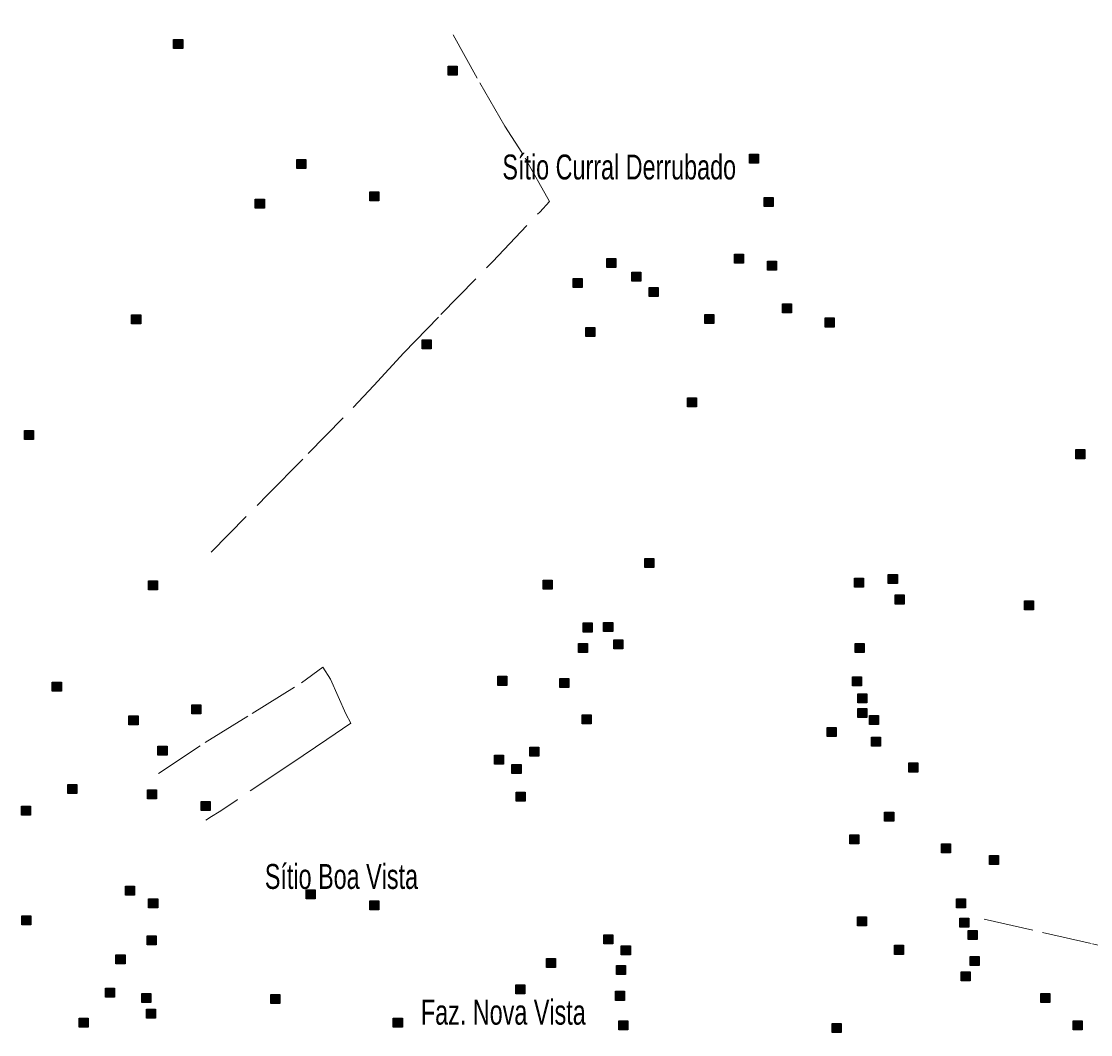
# Model space of a CAD drawing. Extents: x 445.6 to 500, y 8618.1 to 8673.4.
# Drawn here: x 453.66 to 460.52, y 8666.9 to 8673.4 of the extents above; entities that cross this region are included whole.
import ezdxf
from ezdxf.enums import TextEntityAlignment as Align

# ---------------------------------------------------------------- set-up
doc = ezdxf.new("R2010")
doc.units = 0
doc.header["$LTSCALE"] = 0.064
doc.linetypes.add('DOT_DASHED', pattern=[7.7, 5, -1.2, 0.3, -1.2])
doc.layers.add('2', color=7, linetype='Continuous', lineweight=25)
doc.layers.add('22', color=7, linetype='DOT_DASHED', lineweight=13)
doc.layers.add('61', color=7, linetype='Continuous')

msp = doc.modelspace()

# ---------------------------------------------------------------- hatches: boundary and pattern name
at = {"layer": '2'}
for points in [[(454.639, 8673.2829), (454.697, 8673.2829), (454.697, 8673.2249), (454.639, 8673.2249)], [(456.3999, 8673.113), (456.4579, 8673.113), (456.4579, 8673.055), (456.3999, 8673.055)], [(455.4294, 8672.5139), (455.4874, 8672.5139), (455.4874, 8672.4559), (455.4294, 8672.4559)], [(458.3303, 8672.5481), (458.3883, 8672.5481), (458.3883, 8672.4901), (458.3303, 8672.4901)], [(455.8966, 8672.3066), (455.9546, 8672.3066), (455.9546, 8672.2486), (455.8966, 8672.2486)], [(455.1625, 8672.2598), (455.2205, 8672.2598), (455.2205, 8672.2018), (455.1625, 8672.2018)], [(458.4248, 8672.2703), (458.4828, 8672.2703), (458.4828, 8672.2123), (458.4248, 8672.2123)], [(457.417, 8671.8794), (457.475, 8671.8794), (457.475, 8671.8214), (457.417, 8671.8214)], [(458.2345, 8671.9065), (458.2925, 8671.9065), (458.2925, 8671.8485), (458.2345, 8671.8485)], [(458.4473, 8671.8624), (458.5053, 8671.8624), (458.5053, 8671.8044), (458.4473, 8671.8044)], [(457.2009, 8671.7506), (457.2589, 8671.7506), (457.2589, 8671.6926), (457.2009, 8671.6926)], [(457.5758, 8671.7913), (457.6338, 8671.7913), (457.6338, 8671.7333), (457.5758, 8671.7333)], [(457.6872, 8671.6935), (457.7452, 8671.6935), (457.7452, 8671.6355), (457.6872, 8671.6355)], [(458.5419, 8671.588), (458.5999, 8671.588), (458.5999, 8671.53), (458.5419, 8671.53)], [(454.3697, 8671.517), (454.4277, 8671.517), (454.4277, 8671.459), (454.3697, 8671.459)], [(458.0453, 8671.5202), (458.1033, 8671.5202), (458.1033, 8671.4622), (458.0453, 8671.4622)], [(458.8167, 8671.4973), (458.8747, 8671.4973), (458.8747, 8671.4393), (458.8167, 8671.4393)], [(457.2819, 8671.4355), (457.3399, 8671.4355), (457.3399, 8671.3775), (457.2819, 8671.3775)], [(456.233, 8671.3579), (456.291, 8671.3579), (456.291, 8671.2999), (456.233, 8671.2999)], [(457.9339, 8670.9849), (457.9919, 8670.9849), (457.9919, 8670.9269), (457.9339, 8670.9269)], [(453.6823, 8670.7749), (453.7403, 8670.7749), (453.7403, 8670.7169), (453.6823, 8670.7169)], [(460.424, 8670.6529), (460.482, 8670.6529), (460.482, 8670.5949), (460.424, 8670.5949)], [(457.6596, 8669.9546), (457.7176, 8669.9546), (457.7176, 8669.8966), (457.6596, 8669.8966)], [(459.0051, 8669.8294), (459.0631, 8669.8294), (459.0631, 8669.7714), (459.0051, 8669.7714)], [(459.2213, 8669.8531), (459.2793, 8669.8531), (459.2793, 8669.7951), (459.2213, 8669.7951)], [(454.4777, 8669.8125), (454.5357, 8669.8125), (454.5357, 8669.7545), (454.4777, 8669.7545)], [(457.0077, 8669.8157), (457.0657, 8669.8157), (457.0657, 8669.7577), (457.0077, 8669.7577)], [(459.2652, 8669.7209), (459.3232, 8669.7209), (459.3232, 8669.6629), (459.2652, 8669.6629)], [(460.095, 8669.6837), (460.153, 8669.6837), (460.153, 8669.6257), (460.095, 8669.6257)], [(457.2644, 8669.5413), (457.3224, 8669.5413), (457.3224, 8669.4833), (457.2644, 8669.4833)], [(457.3961, 8669.5447), (457.4541, 8669.5447), (457.4541, 8669.4867), (457.3961, 8669.4867)], [(457.4603, 8669.4329), (457.5183, 8669.4329), (457.5183, 8669.3749), (457.4603, 8669.3749)], [(457.234, 8669.4091), (457.292, 8669.4091), (457.292, 8669.3511), (457.234, 8669.3511)], [(459.0085, 8669.4092), (459.0665, 8669.4092), (459.0665, 8669.3512), (459.0085, 8669.3512)], [(453.8609, 8669.1624), (453.9189, 8669.1624), (453.9189, 8669.1044), (453.8609, 8669.1044)], [(456.7172, 8669.1991), (456.7752, 8669.1991), (456.7752, 8669.1411), (456.7172, 8669.1411)], [(457.1158, 8669.1855), (457.1738, 8669.1855), (457.1738, 8669.1275), (457.1158, 8669.1275)], [(458.9916, 8669.1958), (459.0496, 8669.1958), (459.0496, 8669.1378), (458.9916, 8669.1378)], [(459.0254, 8669.0874), (459.0834, 8669.0874), (459.0834, 8669.0294), (459.0254, 8669.0294)], [(454.7547, 8669.0164), (454.8127, 8669.0164), (454.8127, 8668.9584), (454.7547, 8668.9584)], [(454.3527, 8668.9452), (454.4107, 8668.9452), (454.4107, 8668.8872), (454.3527, 8668.8872)], [(457.2576, 8668.9518), (457.3156, 8668.9518), (457.3156, 8668.8938), (457.2576, 8668.8938)], [(459.0254, 8668.9925), (459.0834, 8668.9925), (459.0834, 8668.9345), (459.0254, 8668.9345)], [(459.0997, 8668.9485), (459.1577, 8668.9485), (459.1577, 8668.8905), (459.0997, 8668.8905)], [(458.8295, 8668.8705), (458.8875, 8668.8705), (458.8875, 8668.8125), (458.8295, 8668.8125)], [(459.1132, 8668.8096), (459.1712, 8668.8096), (459.1712, 8668.7516), (459.1132, 8668.7516)], [(454.5385, 8668.7521), (454.5965, 8668.7521), (454.5965, 8668.6941), (454.5385, 8668.6941)], [(456.9232, 8668.7451), (456.9812, 8668.7451), (456.9812, 8668.6871), (456.9232, 8668.6871)], [(456.6969, 8668.6943), (456.7549, 8668.6943), (456.7549, 8668.6363), (456.6969, 8668.6363)], [(456.8084, 8668.6333), (456.8664, 8668.6333), (456.8664, 8668.5753), (456.8084, 8668.5753)], [(459.353, 8668.6435), (459.411, 8668.6435), (459.411, 8668.5855), (459.353, 8668.5855)], [(453.9609, 8668.5048), (454.0189, 8668.5048), (454.0189, 8668.4468), (453.9609, 8668.4468)], [(454.4709, 8668.4709), (454.5289, 8668.4709), (454.5289, 8668.4129), (454.4709, 8668.4129)], [(456.8354, 8668.4571), (456.8934, 8668.4571), (456.8934, 8668.3991), (456.8354, 8668.3991)], [(454.8155, 8668.3964), (454.8735, 8668.3964), (454.8735, 8668.3384), (454.8155, 8668.3384)], [(453.6627, 8668.3671), (453.7207, 8668.3671), (453.7207, 8668.3091), (453.6627, 8668.3091)], [(459.1977, 8668.3285), (459.2557, 8668.3285), (459.2557, 8668.2705), (459.1977, 8668.2705)], [(458.9747, 8668.1828), (459.0327, 8668.1828), (459.0327, 8668.1248), (458.9747, 8668.1248)], [(459.5625, 8668.1252), (459.6205, 8668.1252), (459.6205, 8668.0672), (459.5625, 8668.0672)], [(459.8706, 8668.05), (459.9286, 8668.05), (459.9286, 8667.992), (459.8706, 8667.992)], [(454.33, 8667.8536), (454.388, 8667.8536), (454.388, 8667.7956), (454.33, 8667.7956)], [(454.4786, 8667.7722), (454.5366, 8667.7722), (454.5366, 8667.7142), (454.4786, 8667.7142)], [(455.4876, 8667.8298), (455.5456, 8667.8298), (455.5456, 8667.7718), (455.4876, 8667.7718)], [(459.6581, 8667.7723), (459.7161, 8667.7723), (459.7161, 8667.7143), (459.6581, 8667.7143)], [(455.8963, 8667.7587), (455.9543, 8667.7587), (455.9543, 8667.7007), (455.8963, 8667.7007)], [(453.6657, 8667.6639), (453.7237, 8667.6639), (453.7237, 8667.6059), (453.6657, 8667.6059)], [(459.0237, 8667.6571), (459.0817, 8667.6571), (459.0817, 8667.5991), (459.0237, 8667.5991)], [(459.6803, 8667.6491), (459.7383, 8667.6491), (459.7383, 8667.5911), (459.6803, 8667.5911)], [(459.7324, 8667.569), (459.7904, 8667.569), (459.7904, 8667.511), (459.7324, 8667.511)], [(454.4685, 8667.5351), (454.5265, 8667.5351), (454.5265, 8667.4771), (454.4685, 8667.4771)], [(457.3967, 8667.5419), (457.4547, 8667.5419), (457.4547, 8667.4839), (457.3967, 8667.4839)], [(457.5093, 8667.4703), (457.5673, 8667.4703), (457.5673, 8667.4123), (457.5093, 8667.4123)], [(459.2601, 8667.4741), (459.3181, 8667.4741), (459.3181, 8667.4161), (459.2601, 8667.4161)], [(454.2692, 8667.4131), (454.3272, 8667.4131), (454.3272, 8667.3551), (454.2692, 8667.3551)], [(457.0297, 8667.389), (457.0877, 8667.389), (457.0877, 8667.331), (457.0297, 8667.331)], [(459.7459, 8667.403), (459.8039, 8667.403), (459.8039, 8667.345), (459.7459, 8667.345)], [(457.4789, 8667.345), (457.5369, 8667.345), (457.5369, 8667.287), (457.4789, 8667.287)], [(459.6885, 8667.3047), (459.7465, 8667.3047), (459.7465, 8667.2467), (459.6885, 8667.2467)], [(456.8326, 8667.22), (456.8906, 8667.22), (456.8906, 8667.162), (456.8326, 8667.162)], [(454.2016, 8667.1997), (454.2596, 8667.1997), (454.2596, 8667.1417), (454.2016, 8667.1417)], [(454.4347, 8667.1658), (454.4927, 8667.1658), (454.4927, 8667.1078), (454.4347, 8667.1078)], [(455.2613, 8667.159), (455.3193, 8667.159), (455.3193, 8667.101), (455.2613, 8667.101)], [(457.4722, 8667.179), (457.5302, 8667.179), (457.5302, 8667.121), (457.4722, 8667.121)], [(460.1986, 8667.1658), (460.2566, 8667.1658), (460.2566, 8667.1078), (460.1986, 8667.1078)], [(454.4651, 8667.0641), (454.5231, 8667.0641), (454.5231, 8667.0061), (454.4651, 8667.0061)], [(454.0338, 8667.0066), (454.0918, 8667.0066), (454.0918, 8666.9486), (454.0338, 8666.9486)], [(456.0474, 8667.0065), (456.1054, 8667.0065), (456.1054, 8666.9485), (456.0474, 8666.9485)], [(457.4924, 8666.9892), (457.5504, 8666.9892), (457.5504, 8666.9312), (457.4924, 8666.9312)], [(458.8615, 8666.9727), (458.9195, 8666.9727), (458.9195, 8666.9147), (458.8615, 8666.9147)], [(460.4058, 8666.9896), (460.4638, 8666.9896), (460.4638, 8666.9316), (460.4058, 8666.9316)]]:
    msp.add_hatch(color=256, dxfattribs=at).paths.add_polyline_path(points)

# ---------------------------------------------------------------- linework, layer by layer
for points in [[(454.639, 8673.2829), (454.697, 8673.2829), (454.697, 8673.2249), (454.639, 8673.2249)], [(456.3999, 8673.113), (456.4579, 8673.113), (456.4579, 8673.055), (456.3999, 8673.055)], [(455.4294, 8672.5139), (455.4874, 8672.5139), (455.4874, 8672.4559), (455.4294, 8672.4559)], [(458.3303, 8672.5481), (458.3883, 8672.5481), (458.3883, 8672.4901), (458.3303, 8672.4901)], [(455.8966, 8672.3066), (455.9546, 8672.3066), (455.9546, 8672.2486), (455.8966, 8672.2486)], [(455.1625, 8672.2598), (455.2205, 8672.2598), (455.2205, 8672.2018), (455.1625, 8672.2018)], [(458.4248, 8672.2703), (458.4828, 8672.2703), (458.4828, 8672.2123), (458.4248, 8672.2123)], [(457.417, 8671.8794), (457.475, 8671.8794), (457.475, 8671.8214), (457.417, 8671.8214)], [(458.2345, 8671.9065), (458.2925, 8671.9065), (458.2925, 8671.8485), (458.2345, 8671.8485)], [(458.4473, 8671.8624), (458.5053, 8671.8624), (458.5053, 8671.8044), (458.4473, 8671.8044)], [(457.2009, 8671.7506), (457.2589, 8671.7506), (457.2589, 8671.6926), (457.2009, 8671.6926)], [(457.5758, 8671.7913), (457.6338, 8671.7913), (457.6338, 8671.7333), (457.5758, 8671.7333)], [(457.6872, 8671.6935), (457.7452, 8671.6935), (457.7452, 8671.6355), (457.6872, 8671.6355)], [(458.5419, 8671.588), (458.5999, 8671.588), (458.5999, 8671.53), (458.5419, 8671.53)], [(454.3697, 8671.517), (454.4277, 8671.517), (454.4277, 8671.459), (454.3697, 8671.459)], [(458.0453, 8671.5202), (458.1033, 8671.5202), (458.1033, 8671.4622), (458.0453, 8671.4622)], [(458.8167, 8671.4973), (458.8747, 8671.4973), (458.8747, 8671.4393), (458.8167, 8671.4393)], [(457.2819, 8671.4355), (457.3399, 8671.4355), (457.3399, 8671.3775), (457.2819, 8671.3775)], [(456.233, 8671.3579), (456.291, 8671.3579), (456.291, 8671.2999), (456.233, 8671.2999)], [(457.9339, 8670.9849), (457.9919, 8670.9849), (457.9919, 8670.9269), (457.9339, 8670.9269)], [(453.6823, 8670.7749), (453.7403, 8670.7749), (453.7403, 8670.7169), (453.6823, 8670.7169)], [(460.424, 8670.6529), (460.482, 8670.6529), (460.482, 8670.5949), (460.424, 8670.5949)], [(457.6596, 8669.9546), (457.7176, 8669.9546), (457.7176, 8669.8966), (457.6596, 8669.8966)], [(459.0051, 8669.8294), (459.0631, 8669.8294), (459.0631, 8669.7714), (459.0051, 8669.7714)], [(459.2213, 8669.8531), (459.2793, 8669.8531), (459.2793, 8669.7951), (459.2213, 8669.7951)], [(454.4777, 8669.8125), (454.5357, 8669.8125), (454.5357, 8669.7545), (454.4777, 8669.7545)], [(457.0077, 8669.8157), (457.0657, 8669.8157), (457.0657, 8669.7577), (457.0077, 8669.7577)], [(459.2652, 8669.7209), (459.3232, 8669.7209), (459.3232, 8669.6629), (459.2652, 8669.6629)], [(460.095, 8669.6837), (460.153, 8669.6837), (460.153, 8669.6257), (460.095, 8669.6257)], [(457.2644, 8669.5413), (457.3224, 8669.5413), (457.3224, 8669.4833), (457.2644, 8669.4833)], [(457.3961, 8669.5447), (457.4541, 8669.5447), (457.4541, 8669.4867), (457.3961, 8669.4867)], [(457.4603, 8669.4329), (457.5183, 8669.4329), (457.5183, 8669.3749), (457.4603, 8669.3749)], [(457.234, 8669.4091), (457.292, 8669.4091), (457.292, 8669.3511), (457.234, 8669.3511)], [(459.0085, 8669.4092), (459.0665, 8669.4092), (459.0665, 8669.3512), (459.0085, 8669.3512)], [(453.8609, 8669.1624), (453.9189, 8669.1624), (453.9189, 8669.1044), (453.8609, 8669.1044)], [(456.7172, 8669.1991), (456.7752, 8669.1991), (456.7752, 8669.1411), (456.7172, 8669.1411)], [(457.1158, 8669.1855), (457.1738, 8669.1855), (457.1738, 8669.1275), (457.1158, 8669.1275)], [(458.9916, 8669.1958), (459.0496, 8669.1958), (459.0496, 8669.1378), (458.9916, 8669.1378)], [(459.0254, 8669.0874), (459.0834, 8669.0874), (459.0834, 8669.0294), (459.0254, 8669.0294)], [(454.7547, 8669.0164), (454.8127, 8669.0164), (454.8127, 8668.9584), (454.7547, 8668.9584)], [(454.3527, 8668.9452), (454.4107, 8668.9452), (454.4107, 8668.8872), (454.3527, 8668.8872)], [(457.2576, 8668.9518), (457.3156, 8668.9518), (457.3156, 8668.8938), (457.2576, 8668.8938)], [(459.0254, 8668.9925), (459.0834, 8668.9925), (459.0834, 8668.9345), (459.0254, 8668.9345)], [(459.0997, 8668.9485), (459.1577, 8668.9485), (459.1577, 8668.8905), (459.0997, 8668.8905)], [(458.8295, 8668.8705), (458.8875, 8668.8705), (458.8875, 8668.8125), (458.8295, 8668.8125)], [(459.1132, 8668.8096), (459.1712, 8668.8096), (459.1712, 8668.7516), (459.1132, 8668.7516)], [(454.5385, 8668.7521), (454.5965, 8668.7521), (454.5965, 8668.6941), (454.5385, 8668.6941)], [(456.9232, 8668.7451), (456.9812, 8668.7451), (456.9812, 8668.6871), (456.9232, 8668.6871)], [(456.6969, 8668.6943), (456.7549, 8668.6943), (456.7549, 8668.6363), (456.6969, 8668.6363)], [(456.8084, 8668.6333), (456.8664, 8668.6333), (456.8664, 8668.5753), (456.8084, 8668.5753)], [(459.353, 8668.6435), (459.411, 8668.6435), (459.411, 8668.5855), (459.353, 8668.5855)], [(453.9609, 8668.5048), (454.0189, 8668.5048), (454.0189, 8668.4468), (453.9609, 8668.4468)], [(454.4709, 8668.4709), (454.5289, 8668.4709), (454.5289, 8668.4129), (454.4709, 8668.4129)], [(456.8354, 8668.4571), (456.8934, 8668.4571), (456.8934, 8668.3991), (456.8354, 8668.3991)], [(454.8155, 8668.3964), (454.8735, 8668.3964), (454.8735, 8668.3384), (454.8155, 8668.3384)], [(453.6627, 8668.3671), (453.7207, 8668.3671), (453.7207, 8668.3091), (453.6627, 8668.3091)], [(459.1977, 8668.3285), (459.2557, 8668.3285), (459.2557, 8668.2705), (459.1977, 8668.2705)], [(458.9747, 8668.1828), (459.0327, 8668.1828), (459.0327, 8668.1248), (458.9747, 8668.1248)], [(459.5625, 8668.1252), (459.6205, 8668.1252), (459.6205, 8668.0672), (459.5625, 8668.0672)], [(459.8706, 8668.05), (459.9286, 8668.05), (459.9286, 8667.992), (459.8706, 8667.992)], [(454.33, 8667.8536), (454.388, 8667.8536), (454.388, 8667.7956), (454.33, 8667.7956)], [(454.4786, 8667.7722), (454.5366, 8667.7722), (454.5366, 8667.7142), (454.4786, 8667.7142)], [(455.4876, 8667.8298), (455.5456, 8667.8298), (455.5456, 8667.7718), (455.4876, 8667.7718)], [(459.6581, 8667.7723), (459.7161, 8667.7723), (459.7161, 8667.7143), (459.6581, 8667.7143)], [(455.8963, 8667.7587), (455.9543, 8667.7587), (455.9543, 8667.7007), (455.8963, 8667.7007)], [(453.6657, 8667.6639), (453.7237, 8667.6639), (453.7237, 8667.6059), (453.6657, 8667.6059)], [(459.0237, 8667.6571), (459.0817, 8667.6571), (459.0817, 8667.5991), (459.0237, 8667.5991)], [(459.6803, 8667.6491), (459.7383, 8667.6491), (459.7383, 8667.5911), (459.6803, 8667.5911)], [(459.7324, 8667.569), (459.7904, 8667.569), (459.7904, 8667.511), (459.7324, 8667.511)], [(454.4685, 8667.5351), (454.5265, 8667.5351), (454.5265, 8667.4771), (454.4685, 8667.4771)], [(457.3967, 8667.5419), (457.4547, 8667.5419), (457.4547, 8667.4839), (457.3967, 8667.4839)], [(457.5093, 8667.4703), (457.5673, 8667.4703), (457.5673, 8667.4123), (457.5093, 8667.4123)], [(459.2601, 8667.4741), (459.3181, 8667.4741), (459.3181, 8667.4161), (459.2601, 8667.4161)], [(454.2692, 8667.4131), (454.3272, 8667.4131), (454.3272, 8667.3551), (454.2692, 8667.3551)], [(457.0297, 8667.389), (457.0877, 8667.389), (457.0877, 8667.331), (457.0297, 8667.331)], [(459.7459, 8667.403), (459.8039, 8667.403), (459.8039, 8667.345), (459.7459, 8667.345)], [(457.4789, 8667.345), (457.5369, 8667.345), (457.5369, 8667.287), (457.4789, 8667.287)], [(459.6885, 8667.3047), (459.7465, 8667.3047), (459.7465, 8667.2467), (459.6885, 8667.2467)], [(456.8326, 8667.22), (456.8906, 8667.22), (456.8906, 8667.162), (456.8326, 8667.162)], [(454.2016, 8667.1997), (454.2596, 8667.1997), (454.2596, 8667.1417), (454.2016, 8667.1417)], [(454.4347, 8667.1658), (454.4927, 8667.1658), (454.4927, 8667.1078), (454.4347, 8667.1078)], [(455.2613, 8667.159), (455.3193, 8667.159), (455.3193, 8667.101), (455.2613, 8667.101)], [(457.4722, 8667.179), (457.5302, 8667.179), (457.5302, 8667.121), (457.4722, 8667.121)], [(460.1986, 8667.1658), (460.2566, 8667.1658), (460.2566, 8667.1078), (460.1986, 8667.1078)], [(454.4651, 8667.0641), (454.5231, 8667.0641), (454.5231, 8667.0061), (454.4651, 8667.0061)], [(454.0338, 8667.0066), (454.0918, 8667.0066), (454.0918, 8666.9486), (454.0338, 8666.9486)], [(456.0474, 8667.0065), (456.1054, 8667.0065), (456.1054, 8666.9485), (456.0474, 8666.9485)], [(457.4924, 8666.9892), (457.5504, 8666.9892), (457.5504, 8666.9312), (457.4924, 8666.9312)], [(458.8615, 8666.9727), (458.9195, 8666.9727), (458.9195, 8666.9147), (458.8615, 8666.9147)], [(460.4058, 8666.9896), (460.4638, 8666.9896), (460.4638, 8666.9316), (460.4058, 8666.9316)]]:
    msp.add_lwpolyline(points, close=True, dxfattribs=at)
at = {"layer": '22'}
for points in [[(454.8787, 8669.996), (455.2436, 8670.3646), (455.5025, 8670.6273), (455.791, 8670.9239), (455.9226, 8671.0637), (456.1144, 8671.2733), (456.352, 8671.5191), (456.683, 8671.858), (456.9863, 8672.1769), (457.0498, 8672.244), (456.871, 8672.5593), (456.7627, 8672.7271), (456.586, 8673.0343), (456.3834, 8673.3994)], [(454.5421, 8668.575), (454.8418, 8668.7756), (455.1418, 8668.96), (455.4584, 8669.1576), (455.5947, 8669.2575), (455.6442, 8669.1817), (455.7431, 8668.9578), (455.7761, 8668.8986), (455.6211, 8668.7932), (455.3969, 8668.6417), (455.0432, 8668.406), (454.9311, 8668.3303), (454.8816, 8668.3007), (454.8443, 8668.2757)], [(459.8363, 8667.6409), (460.2101, 8667.5563), (460.5302, 8667.4836), (460.809, 8667.4207), (460.8372, 8667.4129), (460.8493, 8667.1078), (460.8469, 8666.8609), (460.8609, 8666.5929), (460.8658, 8666.3217), (460.8732, 8666.1144), (460.8877, 8665.7585), (460.8831, 8665.5131)]]:
    msp.add_lwpolyline(points, dxfattribs=at)

# ---------------------------------------------------------------- texts
at = {"layer": '61', "width": 0.7}
msp.add_text('Sítio Curral Derrubado', height=0.16, dxfattribs=at).set_placement((458.2451, 8672.3855), align=Align.RIGHT)
for s, p in [('Sítio Boa Vista', (455.2237, 8667.8358)), ('Faz. Nova Vista', (456.2242, 8666.9652))]:
    msp.add_text(s, height=0.16, dxfattribs=at).set_placement(p)

doc.saveas('drawing.dxf')
